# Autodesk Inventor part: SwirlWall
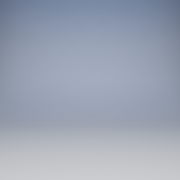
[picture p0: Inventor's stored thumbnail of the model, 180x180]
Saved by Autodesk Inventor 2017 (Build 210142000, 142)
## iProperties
Created: 2017-05
Part Number: SwirlWall
Material: Generic
Document SubType Name: Modeling
Designer: 1460374
Density: 1 g/cm^3
Appearance: Default
Author: 1460374
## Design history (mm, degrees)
sketch "Sketch1"
  geometry: L1 (-26.808, 32.526)-(-40.164, 28.33) reference; L2 (24.03, -31.119)-(12.478, -34.749); L3 (12.478, -34.749)-(-40.164, 28.33); 1 further point
  constraints: 4 end point
extrude "Extrusion1" new body sketch "Sketch1" distance "d0" = 3.175; taper "d1" = 0 deg
body "Solid1"
node "Reference1"
node "Reference2"
